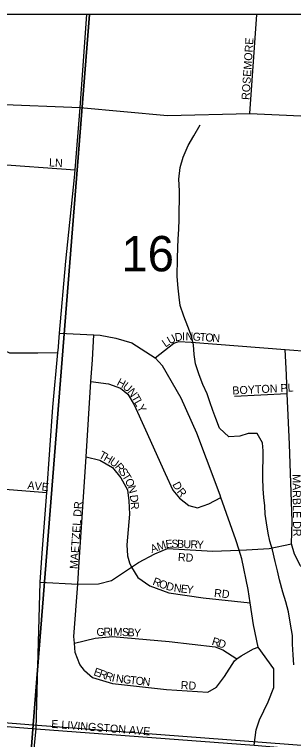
# Model space of a CAD drawing. Extents: x 0 to 34, y 0 to 22.
# Drawn here: x 6.877 to 7.208, y 20.042 to 20.9 of the extents above; entities that cross this region are included whole.
import ezdxf

# ---------------------------------------------------------------- set-up
doc = ezdxf.new("R2010")
doc.units = 0
for name, color, linetype in [('GM_X_City_Street', 7, 'Continuous'), ('GM_X_City_Street_Text', 7, 'Continuous'), ('GM_X_Minor_River', 7, 'Continuous'), ('GM_X_Section', 7, 'Continuous'), ('GM_X_Section_Text', 7, 'Continuous'), ('GM_X_State_Route', 7, 'Continuous'), ('GM_X_Township', 7, 'Continuous'), ('GM_X_US_Route', 7, 'Continuous')]:
    doc.layers.add(name, color=color, linetype=linetype)

msp = doc.modelspace()

# ---------------------------------------------------------------- linework, layer by layer
at = {"layer": 'GM_X_City_Street'}
for points in [[(7.15585, 20.78303), (7.16427, 20.9)], [(6.72641, 20.73289), (6.84902, 20.72339), (6.85159, 20.72319), (6.94923, 20.7163)], [(6.17619, 20.58057), (6.27866, 20.57192), (6.37132, 20.56521), (6.42912, 20.56102), (6.4848, 20.557), (6.5056, 20.55549), (6.54038, 20.55273), (6.59428, 20.54845), (6.63341, 20.54535), (6.6512, 20.54397), (6.71158, 20.53928), (6.74271, 20.53687), (6.79375, 20.53274), (6.80507, 20.53089), (6.82488, 20.52121), (6.85068, 20.50907), (6.87164, 20.49973), (6.90498, 20.49953), (6.92871, 20.50006)], [(6.93074, 20.52293), (6.97121, 20.52093), (6.97874, 20.52056), (6.99722, 20.51699), (7.01638, 20.51149), (7.04392, 20.49399), (7.05236, 20.48426)], [(6.96956, 20.49158), (6.97121, 20.52093)], [(7.04392, 20.49399), (7.06603, 20.5112), (7.07176, 20.51293), (7.08653, 20.51251), (7.19765, 20.50364), (7.25821, 20.49881)], [(7.19911, 20.47356), (7.19765, 20.50364)], [(6.96042, 20.1239), (6.95456, 20.1309), (6.94928, 20.14511), (6.94827, 20.15631), (6.94756, 20.16415), (6.95222, 20.22594), (6.95373, 20.24599), (6.96216, 20.37673), (6.96791, 20.46584), (6.96956, 20.49158)], [(7.16116, 20.03551), (7.1633, 20.05354), (7.16717, 20.06546), (7.1776, 20.08691), (7.18415, 20.10359), (7.18415, 20.12593), (7.16589, 20.15149), (7.16021, 20.1781), (7.15626, 20.20392), (7.15385, 20.2196), (7.14629, 20.25617), (7.14315, 20.26614), (7.13933, 20.27829), (7.12148, 20.32875), (7.12057, 20.33131), (7.10451, 20.37416), (7.09327, 20.40485), (7.07475, 20.44602), (7.05236, 20.48426)], [(7.25053, 20.23441), (7.23761, 20.23285), (7.22565, 20.23851), (7.21568, 20.24753), (7.20888, 20.2614), (7.20506, 20.27366), (7.20585, 20.30059), (7.2028, 20.39182), (7.20013, 20.45105), (7.19911, 20.47356)], [(6.96791, 20.46584), (6.98844, 20.46295), (7.0027, 20.45797), (7.01159, 20.45088), (7.01918, 20.43813), (7.03235, 20.40851), (7.05549, 20.35696), (7.06478, 20.33733), (7.07245, 20.32762), (7.08357, 20.31894), (7.09411, 20.31636), (7.10751, 20.32091), (7.12148, 20.32875)], [(7.20013, 20.45105), (7.13773, 20.448)], [(6.96216, 20.37673), (6.97825, 20.37287), (6.99354, 20.36407), (7.00342, 20.35201), (7.01097, 20.33775), (7.01286, 20.32478), (7.01354, 20.30881), (7.01021, 20.27246), (7.01097, 20.25953), (7.01338, 20.2511), (7.01597, 20.2462)], [(6.7745, 20.32636), (6.78887, 20.33809), (6.79695, 20.34354), (6.80985, 20.3428), (6.86125, 20.33878), (6.91556, 20.33454)], [(6.90784, 20.22843), (6.95222, 20.22594), (6.97665, 20.22634), (6.99231, 20.23044), (7.01597, 20.2462), (7.02401, 20.25155), (7.04326, 20.26201), (7.05859, 20.26802), (7.11195, 20.26496), (7.14315, 20.26614), (7.15179, 20.26646), (7.17875, 20.26835), (7.20506, 20.27366)], [(7.01597, 20.2462), (7.02349, 20.23372), (7.03762, 20.2242), (7.06012, 20.21595), (7.1005, 20.20985), (7.15626, 20.20392)], [(6.94827, 20.15631), (6.9729, 20.16227), (6.99342, 20.16396), (7.06034, 20.15823), (7.11473, 20.15171), (7.12373, 20.14842), (7.1405, 20.13755)], [(6.96042, 20.1239), (6.96965, 20.11566), (6.99333, 20.10852), (7.05717, 20.10135), (7.10597, 20.09805), (7.11638, 20.1042), (7.12585, 20.11684), (7.13776, 20.13548), (7.1405, 20.13755), (7.14551, 20.14134), (7.16015, 20.14964), (7.16589, 20.15149)], [(5.88898, 20.13374), (6.0182, 20.12601), (6.12873, 20.11707), (6.18862, 20.1117), (6.3069, 20.10217), (6.39285, 20.09457), (6.47955, 20.0881), (6.49452, 20.08705), (6.61958, 20.07678), (6.81532, 20.06158), (6.83409, 20.06038), (6.90291, 20.05472)], [(6.90291, 20.05472), (6.90291, 20.05472), (7.16116, 20.03551), (7.24419, 20.02836), (7.41893, 20.0151), (7.48652, 20.0093)]]:
    msp.add_lwpolyline(points, dxfattribs=at)
at = {"layer": 'GM_X_Minor_River'}
msp.add_lwpolyline([(7.20784, 20.13053), (7.20716, 20.14231), (7.20648, 20.15484), (7.20616, 20.16509), (7.20398, 20.17877), (7.20142, 20.1932), (7.19847, 20.20499), (7.19475, 20.2164), (7.19106, 20.23123), (7.18848, 20.24187), (7.1859, 20.25289), (7.18258, 20.26658), (7.17962, 20.27685), (7.17741, 20.28635), (7.1756, 20.2985), (7.17415, 20.30876), (7.17345, 20.31863), (7.17238, 20.32851), (7.17168, 20.33876), (7.17138, 20.35167), (7.17158, 20.38393), (7.17088, 20.39342), (7.16452, 20.40409), (7.15393, 20.40416), (7.14408, 20.40118), (7.13084, 20.4005), (7.11994, 20.41043), (7.11547, 20.42185), (7.11213, 20.43136), (7.10841, 20.44163), (7.10544, 20.45113), (7.10022, 20.46217), (7.09575, 20.47359), (7.09167, 20.48652), (7.08985, 20.49792), (7.08916, 20.50931), (7.08695, 20.51956), (7.08248, 20.53098), (7.07764, 20.54315), (7.07356, 20.5557), (7.07211, 20.56558), (7.07104, 20.57621), (7.06999, 20.58988), (7.07012, 20.61114), (7.07058, 20.62442), (7.07102, 20.63428), (7.07185, 20.64604), (7.0723, 20.65742), (7.07236, 20.66691), (7.07282, 20.68171), (7.0725, 20.6912), (7.07183, 20.70525), (7.07343, 20.7189), (7.07691, 20.7314), (7.08305, 20.74503), (7.08954, 20.75638), (7.09719, 20.76961)], dxfattribs=at)
at = {"layer": 'GM_X_Section'}
for p, q in [((6.96615, 20.9), (6.4544, 20.9)), ((7.47668, 20.9), (6.96615, 20.9))]:
    msp.add_line(p, q, dxfattribs=at)
for points in [[(6.4544, 20.9), (6.39308, 20.09979), (6.89954, 20.05948), (6.96615, 20.9)], [(6.96615, 20.9), (6.89954, 20.05948), (7.40469, 20.02134), (7.47668, 20.9)]]:
    msp.add_lwpolyline(points, dxfattribs=at)
for points in [[(6.39308, 20.09979), (6.89954, 20.05948), (6.82179, 19.05189), (6.31814, 19.09172)], [(6.89954, 20.05948), (7.40469, 20.02134), (7.32396, 19.01244), (6.82179, 19.05189)]]:
    msp.add_lwpolyline(points, close=True, dxfattribs=at)
at = {"layer": 'GM_X_State_Route'}
for points in [[(6.95519, 20.7898), (6.96305, 20.9)], [(6.92889, 20.50212), (6.93074, 20.52293), (6.9383, 20.60818), (6.94848, 20.70697), (6.94923, 20.7163), (6.95519, 20.7898)], [(6.90461, 20.11447), (6.90784, 20.22843), (6.91028, 20.26277), (6.91556, 20.33454), (6.92296, 20.43529), (6.92871, 20.50006), (6.92882, 20.50125), (6.92889, 20.50212)], [(6.89924, 20.01577), (6.90291, 20.05472), (6.90461, 20.11447)]]:
    msp.add_lwpolyline(points, dxfattribs=at)
at = {"layer": 'GM_X_Township'}
msp.add_lwpolyline([(9.4, 17.82945), (9.4, 20.9), (4.42993, 20.9)], dxfattribs=at)
at = {"layer": 'GM_X_US_Route'}
for points in [[(5.49118, 20.85512), (5.52807, 20.85345), (5.65258, 20.84779), (5.68974, 20.8454), (5.69384, 20.84521), (5.88349, 20.83613), (6.03241, 20.82919), (6.03369, 20.82914), (6.12003, 20.82625), (6.32153, 20.81951), (6.32492, 20.81934), (6.44983, 20.81341), (6.50608, 20.81127), (6.55995, 20.8089), (6.61605, 20.80495), (6.66585, 20.80248), (6.66772, 20.80239), (6.731, 20.7995), (6.75673, 20.79832), (6.8528, 20.79392), (6.85574, 20.7938), (6.95519, 20.7898)], [(6.95519, 20.7898), (7.05834, 20.78049), (7.15585, 20.78303), (7.25079, 20.7786), (7.26185, 20.77814)]]:
    msp.add_lwpolyline(points, dxfattribs=at)

# ---------------------------------------------------------------- texts
at = {"layer": 'GM_X_City_Street_Text'}
for s, height, rotation, p in [('ROSEMORE', 0.00947, 86.23517, (7.15537, 20.79868)), ('LN', 0.00947, 356.98902, (6.91808, 20.72034)), ('U', 0.00947, 29.20534, (7.06131, 20.5095)), ('D', 0.00947, 8.17955, (7.06772, 20.51327)), ('I', 0.00947, 1.04878, (7.07566, 20.51443)), ('N', 0.00947, 358.95082, (7.07974, 20.51451)), ('G', 0.00947, 356.52318, (7.08796, 20.51436)), ('T', 0.00947, 356.20046, (7.09627, 20.51385)), ('O', 0.00947, 356.17284, (7.10292, 20.51341)), ('N', 0.00947, 356.19817, (7.11124, 20.51285)), ('L', 0.00947, 34.94053, (7.05606, 20.50581)), ('H', 0.00947, 332.53565, (6.99768, 20.46195)), ('U', 0.00947, 320.65062, (7.00464, 20.45839)), ('N', 0.00947, 305.96954, (7.01065, 20.45357)), ('BOYTON PL', 0.00947, 2.9341, (7.13539, 20.45034)), ('T', 0.00947, 299.57207, (7.01539, 20.44706)), ('L', 0.00947, 298.63009, (7.01866, 20.4413)), ('Y', 0.00947, 298.62791, (7.02186, 20.43545)), ('T', 0.00947, 331.1126, (6.97633, 20.37597)), ('H', 0.00947, 331.09824, (6.98216, 20.37275)), ('U', 0.00947, 325.12793, (6.98924, 20.36886)), ('R', 0.00947, 311.01228, (6.99562, 20.3645)), ('S', 0.00947, 307.17045, (7.00043, 20.35898)), ('T', 0.00947, 301.28709, (7.00431, 20.35388)), ('MARBLE DR', 0.00947, 270.6919, (7.20631, 20.3561)), ('AVE', 0.00947, 353.88781, (6.89234, 20.33867)), ('O', 0.00947, 296.29134, (7.00767, 20.34837)), ('D', 0.00947, 298.18823, (7.06388, 20.34407)), ('N', 0.00947, 286.37475, (7.0112, 20.3413)), ('R', 0.00947, 309.38775, (7.06892, 20.33508)), ('D', 0.00947, 276.04334, (7.01392, 20.33129)), ('MAETZEL DR', 0.00947, 86.09921, (6.95215, 20.24367)), ('R', 0.00947, 273.59603, (7.01479, 20.32311)), ('M', 0.00947, 18.67111, (7.04766, 20.26553)), ('E', 0.00947, 6.04761, (7.0566, 20.26861)), ('S', 0.00947, 358.41493, (7.0629, 20.2693)), ('B', 0.00947, 357.88699, (7.06954, 20.26912)), ('U', 0.00947, 357.87971, (7.07703, 20.26884)), ('R', 0.00947, 357.86273, (7.08536, 20.26853)), ('Y', 0.00947, 357.88739, (7.09286, 20.26825)), ('A', 0.00947, 19.68617, (7.03986, 20.26274)), ('RD', 0.00947, 356.98902, (7.07056, 20.25342)), ('R', 0.00947, 338.80733, (7.04008, 20.22564)), ('O', 0.00947, 339.96215, (7.04727, 20.22286)), ('D', 0.00947, 344.76019, (7.05592, 20.21974)), ('N', 0.00947, 353.3671, (7.06548, 20.21726)), ('E', 0.00947, 353.29176, (7.07376, 20.2163)), ('Y', 0.00947, 353.28761, (7.08038, 20.21552)), ('RD', 0.00947, 353.99339, (7.11317, 20.21116)), ('R', 0.00947, 2.38089, (6.98289, 20.16486)), ('I', 0.00947, 0.48073, (6.9903, 20.16517)), ('M', 0.00947, 357.7771, (6.99435, 20.16521)), ('G', 0.00947, 2.40505, (6.97457, 20.16451)), ('S', 0.00947, 357.15806, (7.00431, 20.16482)), ('B', 0.00947, 357.13274, (7.01097, 20.16449)), ('Y', 0.00947, 357.13312, (7.01846, 20.16411)), ('R', 0.00947, 343.32402, (7.11014, 20.15444)), ('D', 0.00947, 342.20787, (7.11728, 20.1523)), ('E', 0.00947, 340.50238, (6.97025, 20.11857)), ('R', 0.00947, 340.52359, (6.97654, 20.11634)), ('R', 0.00947, 340.98214, (6.98369, 20.11382)), ('I', 0.00947, 347.69, (6.99195, 20.11105)), ('N', 0.00947, 353.27737, (6.99701, 20.10999)), ('G', 0.00947, 353.76255, (7.00538, 20.10901)), ('T', 0.00947, 353.79015, (7.01367, 20.1081)), ('O', 0.00947, 353.75876, (7.02029, 20.10738)), ('N', 0.00947, 353.785, (7.02858, 20.10647)), ('RD', 0.00947, 356.98902, (7.07391, 20.102)), ('E LIVINGSTON AVE', 0.0094697, 355.53197, (6.92062, 20.05617))]:
    msp.add_text(s, height=height, rotation=rotation, dxfattribs=at).set_placement(p)
at = {"layer": 'GM_X_Section_Text'}
msp.add_text('16', height=0.041856, rotation=0.00001, dxfattribs=at).set_placement((7.00382, 20.59612))

doc.saveas('drawing.dxf')
